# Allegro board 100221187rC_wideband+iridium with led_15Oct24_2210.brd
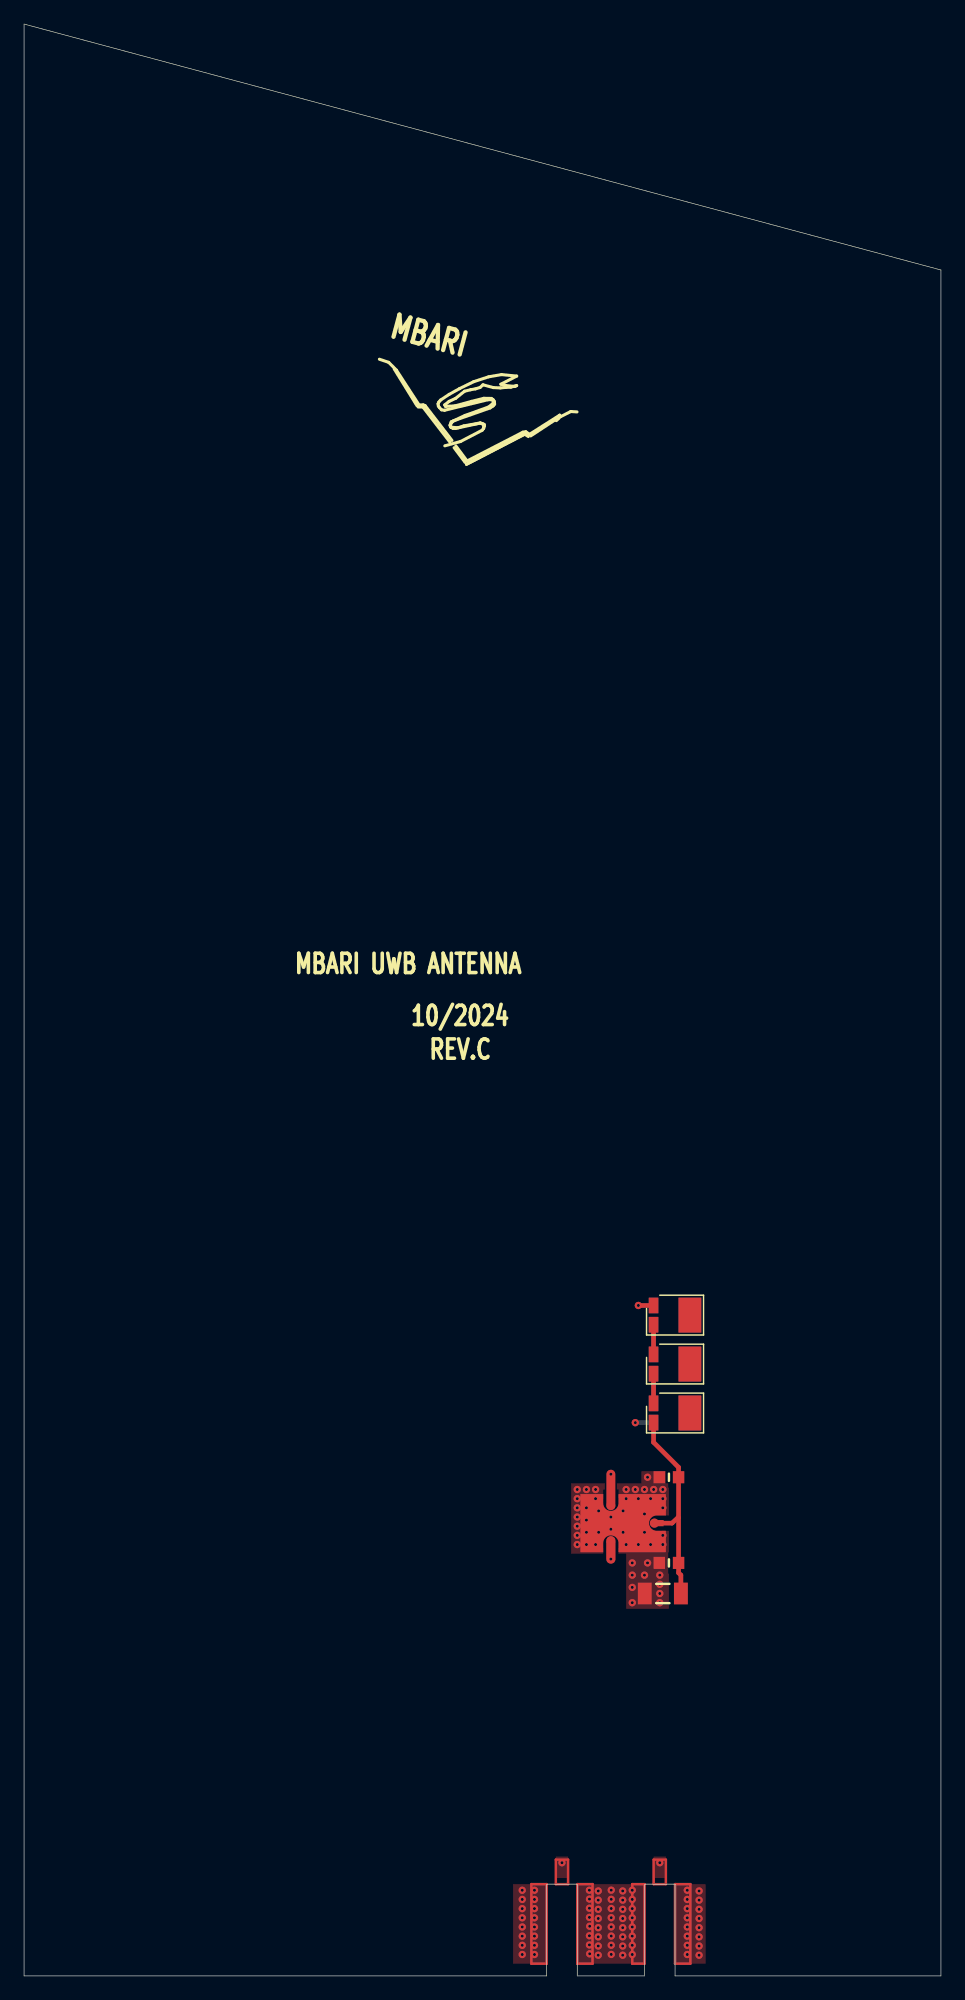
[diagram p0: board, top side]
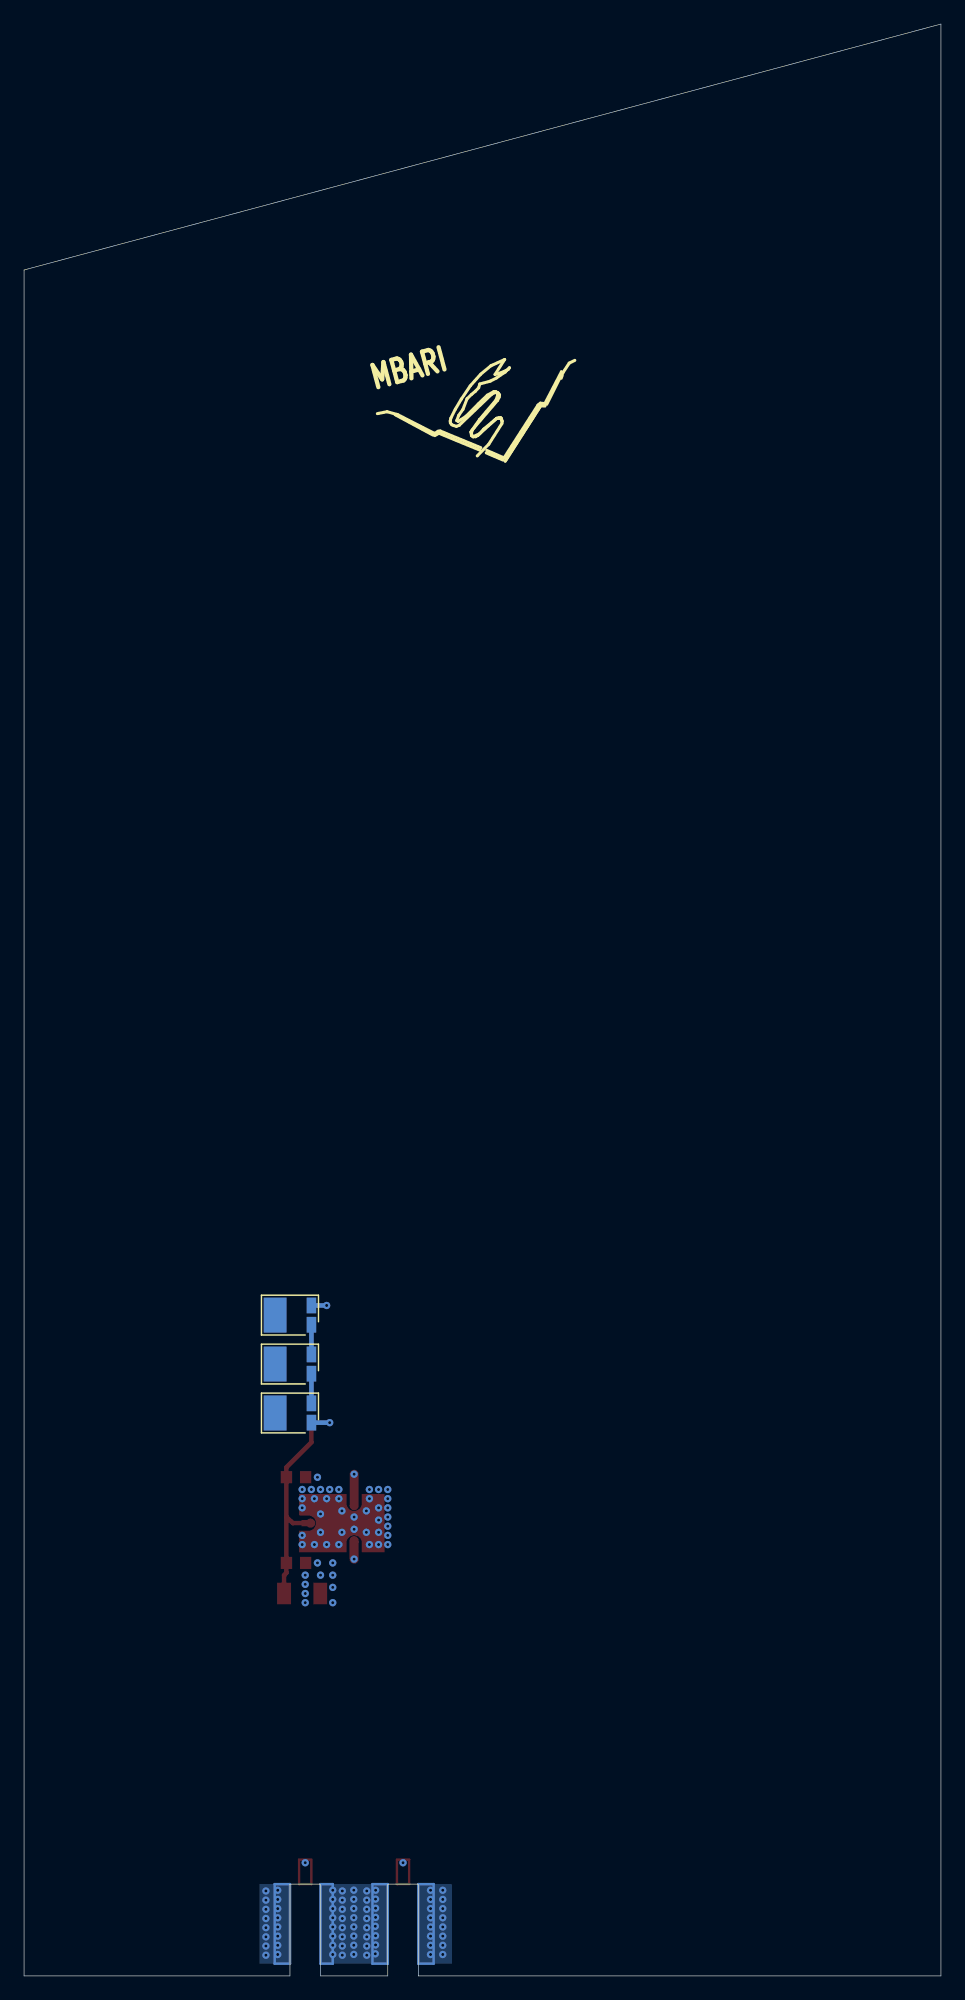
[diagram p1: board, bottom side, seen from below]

Outline 76.2 x 162.05 mm; copper layers: TOP, IN1, IN2, BOTTOM. Coordinates in mm from the lower left corner of the outline.
Outline path: 0,162.05 76.2,141.63 76.2,0 54.1,0 54.1,7.62 51.56,7.62 51.56,0 45.97,0 45.97,7.62 43.43,7.62 43.43,0 0,0 0,162.05

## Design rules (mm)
constraint set DEFAULT: min track width 0.127

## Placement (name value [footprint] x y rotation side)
C1  1.0uF  [CAPC3216X190N]  53.09 31.75 180 top
C2  10,000.0pF  [CAPC1608X87N]  53.59 41.4 180 top
C3  10,000.0pF  [CAPC1608X87N]  53.59 34.29 180 top
D1  LXM2-PH01-0070  [DIODFN449X305X210-3N]  54.1 46.74 0 top
D2  LXM2-PH01-0070  [DIODFN449X305X210-3N]  54.1 50.8 0 top
D3  LXM2-PH01-0070  [DIODFN449X305X210-3N]  54.1 54.86 0 top
D4  LXM2-PH01-0070  [DIODFN449X305X210-3N]  54.1 54.86 0 bottom
D5  LXM2-PH01-0070  [DIODFN449X305X210-3N]  54.1 50.8 0 bottom
D6  LXM2-PH01-0070  [DIODFN449X305X210-3N]  54.1 46.74 0 bottom
NOREF  -  []  12.7 145.54 0 top
NOREF#2  -  []  12.7 0 90 top
NOREF#3  -  []  52.83 0 0 top
NOREF#4  -  []  63.5 0 90 top
NOREF#5  -  []  51.69 0 0 top
NOREF#6  -  []  43.56 0 0 top
NOREF#7  -  []  -116.59 -69.6 0 top
NOREF#8  -  []  -116.59 -69.6 0 top
NOREF#9  -  []  45.85 0 0 top
NOREF#10  -  []  86.11 11.43 0 top
NOREF#11  -  []  39.12 134.37 345 top
NOREF#12  -  []  12.7 0 0 top
NOREF#13  -  []  38.61 134.62 165 bottom
U1  BT-0014SMG  [MARKI_BTSM-PDSM]  49.78 37.59 0 top

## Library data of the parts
C1-C3 = CAP
D1-D6 = LED_C1A2
U1 = MARKI_BT-0014SMG-1

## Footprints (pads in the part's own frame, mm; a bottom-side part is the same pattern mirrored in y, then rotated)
CAPC1608X87N
  rect 0.95x1.001 smd: 1(-0.8,0) 2(0.8,0)
CAPC3216X190N
  rect 1.151x1.801 smd: 1(-1.501,0) 2(1.501,0)
DIODFN449X305X210-3N
  rect 1.89x2.901 smd: (1.234,0)
  rect 0.79x1.3 smd: 1(-1.786,0.8) 2(-1.786,-0.8)
MARKI_BTSM-PDSM
  custom 0.191x0.191 smd: 1(-1.016,-1.651) 2(-1.016,1.651) 3(2.794,0)
  custom 1.206x1.206 smd: 4(0,0)

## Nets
GND_SIGNAL: C1.2 C2.2 C3.2 D6.1(C) U1.4(GND)
LED: C1.1 C2.1 C3.1 D1.2 U1.3
UWB FEEDLINE: U1.2
N06909: U1.1
N07165: D1.1(C) D2.2
N048171: D2.1(C) D3.2
N048451: D3.1(C) D4.2
N048711: D4.1(C) D5.2
N048971: D5.1(C) D6.2

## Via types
v1: diameter 0.61, hole 0.254, TOP to BOTTOM, 127 vias
v2: diameter 0.61, hole 0.254, IN1 to IN2, 1 via

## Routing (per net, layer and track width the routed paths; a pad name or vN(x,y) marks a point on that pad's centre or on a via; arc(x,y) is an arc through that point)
GND_SIGNAL: length 105.5
  IN1 w1.092: v1(52.83,9.4) 52.83,16.37 arc(53.51,19.78) 55.44,22.66 55.44,22.66 arc(58.77,27.65) 59.94,33.53 59.94,66.42 arc(58.56,70.98) 54.88,74.01 38.56,80.82 arc(35.76,83.47) 35.44,87.32 v2(38.1,96.77)
  BOTTOM w0.381: D6.1 v1(50.8,45.94)
  vias: v1(41.4,7.11) v1(41.4,6.35) v1(41.4,5.59) v1(41.4,4.83) v1(41.4,4.06) v1(41.4,3.3) v1(41.4,2.54) v1(41.4,1.78) v1(42.42,7.11) v1(42.42,6.35) v1(42.42,5.59) v1(42.42,4.83) v1(42.42,4.06) v1(42.42,3.3) v1(42.42,2.54) v1(42.42,1.78) v1(45.97,40.39) v1(45.97,39.62) v1(45.97,38.86) v1(45.97,38.1) v1(45.97,37.34) v1(45.97,36.58) v1(45.97,35.81) v1(46.74,40.39) v1(46.74,38.86) v1(46.74,37.85) v1(46.74,36.83) v1(46.74,35.81) v1(46.98,7.11) v1(46.99,6.38) v1(46.99,5.62) v1(46.99,4.86) v1(47.01,4.12) v1(46.99,3.34) v1(46.99,2.57) v1(47.01,1.84) v1(47.5,40.39) v1(47.5,39.62) v1(47.5,35.81) v1(47.72,7.05) v1(47.72,6.29) v1(47.72,5.53) v1(47.72,4.77) v1(47.72,4.01) v1(47.72,3.24) v1(47.72,2.48) v1(47.72,1.72) v1(47.75,38.61) v1(47.75,36.83) v1(48.77,38.1) v1(48.77,37.08) v1(48.8,7.12) v1(48.8,6.36) v1(48.8,5.6) v1(48.8,4.83) v1(48.8,4.07) v1(48.8,3.31) v1(48.8,2.55) v1(48.8,1.79) v1(49.78,38.61) v1(49.78,36.83) v1(49.75,7.05) v1(49.75,6.29) v1(49.75,5.53) v1(49.75,4.77) v1(49.75,4.01) v1(49.75,3.24) v1(49.75,2.48) v1(49.75,1.72) v1(50.04,40.39) v1(50.04,39.62) v1(50.04,35.81) v1(50.55,34.29) v1(50.55,33.27) v1(50.55,32.26) v1(50.55,30.99) v1(50.55,7.11) v1(50.55,6.35) v1(50.55,5.59) v1(50.55,4.83) v1(50.55,4.06) v1(50.55,3.3) v1(50.55,2.54) v1(50.55,1.78) v1(50.8,40.39) v1(51.05,39.62) v1(51.05,35.81) v1(51.56,40.39) v1(51.56,38.35) v1(51.56,36.83) v1(51.56,33.27) v1(51.82,41.4) v1(51.82,34.29) v1(52.07,39.62) v1(52.07,35.81) v1(52.32,40.39) v1(52.83,33.27) v1(52.83,32.51) v1(52.83,31.75) v1(52.83,30.99) v1(53.09,40.39) v1(53.09,39.62) v1(53.09,38.86) v1(53.09,36.58) v1(53.09,35.81) v1(55.12,7.11) v1(55.12,6.35) v1(55.12,5.59) v1(55.12,4.83) v1(55.12,4.06) v1(55.12,3.3) v1(55.12,2.54) v1(55.12,1.78) v1(56.1,7.05) v1(56.1,6.29) v1(56.1,5.53) v1(56.1,4.77) v1(56.1,4.01) v1(56.1,3.24) v1(56.1,2.48) v1(56.1,1.72)
LED: length 17.1
  TOP w0.381: 54.39,38.04 54.34,38.04 53.85,37.59 U1.3 ; 54.39,38.04 C2.1 54.39,42.22 52.32,44.3 D1.2 ; 54.39,38.04 C3.1 54.39,33.47 54.59,33.28 C1.1
UWB FEEDLINE: length 73.1
  TOP w0.737: U1.2 v1(48.77,41.66)
  IN1 w1.092: 28.7,103.12 24.76,88.23 arc(24.79,76.33) 30.74,66.03 44.28,52.5 arc(47.6,47.53) 48.77,41.66
N06909: length 28.2
  TOP w0.762: U1.1 v1(48.77,34.61)
  IN1 w1.092: v1(44.7,9.4) 44.7,25.07 arc(45.23,27.72) 46.74,29.97 arc(48.24,32.22) 48.77,34.88 v1(48.77,34.61)
N07165: length 2.5
  TOP w0.381: D2.2 D1.1
N048171: length 2.5
  TOP w0.381: D3.2 D2.1
N048451: length 2.5
  TOP w0.381: v1(51.05,55.66) D3.1
  BOTTOM w0.381: D3.1 v1(51.05,55.66)
N048711: length 2.5
  BOTTOM w0.381: D4.1 D5.2
N048971: length 2.5
  BOTTOM w0.381: D5.1 D6.2

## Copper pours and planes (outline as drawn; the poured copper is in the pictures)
GND_SIGNAL on TOP: 43.43,1.02 43.43,7.62 40.64,7.62 40.64,1.02
GND_SIGNAL on TOP: 50.04,30.48 50.04,35.05 45.47,35.05 45.47,40.89 51.31,40.89 51.31,41.91 53.34,41.91 53.34,40.89 53.59,40.89 53.59,30.48
GND_SIGNAL on TOP: 53.34,8.13 52.32,8.13 52.32,9.91 53.34,9.91
GND_SIGNAL on TOP: 45.97,7.62 45.97,1.02 51.56,1.02 51.56,7.62
GND_SIGNAL on TOP, BOTTOM: 54.1,7.62 54.1,1.02 56.64,1.02 56.64,7.62
GND_SIGNAL on BOTTOM: 40.64,7.62 40.64,1.02 43.43,1.02 43.43,7.62
GND_SIGNAL on BOTTOM: 45.97,1.02 45.97,7.62 51.56,7.62 51.56,1.02
GND_SIGNAL on IN2: 62.3,83.82 62.68,83.82 62.74,1.31 62.74,1.02 54.1,1.02 54.1,7.62 51.56,7.62 51.56,1.02 45.97,1.02 45.97,7.62 43.43,7.62 43.43,1.02 13.72,1.02 13.72,14.58 13.72,14.58 13.72,106.75 29.98,102.39 29.8,101.72 62.88,92.86 62.03,89.67 31.97,97.72 30.52,92.33 62.3,83.81 ; 2 cut-outs
UWB FEEDLINE on IN1: 62.2,131.03 13.77,144.01 28.64,102.66
N06909 on TOP: 45.21,8.13 44.2,8.13 44.2,9.91 45.21,9.91

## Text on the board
Ref Des/Silkscreen Top: MBARI UWB ANTENNA | 10/2024 | REV.C
XSECTION_CHART: *  PLATING: ENIG | L1: TOP CONDUCTOR - COPPER 2.1 MIL | *  DIELECTRIC - 4003C 32 mil | L2: IN1 CONDUCTOR - COPPER 1.4 MIL | *  DIELECTRIC - 4003C 20 mil | L3: IN2 CONDUCTOR - COPPER 1.4 MIL | L4: BOTTOM CONDUCTOR - COPPER 2.1 MIL | DESIGN CROSS SECTION CHART | ___________________________ | TOTAL THICKNESS 93 MIL | 1-4 | 2-3
PAGE_OUTLINE: CHANGE CABLE INPUT | ENLARGE OUTLINE, | c
DIMENSION: (2x) ADD EDGE PLATING INSIDE | BOTH SLOTS.
DEVICE_TYPE_BOTTOM: FIGURE | FINISHED_SIZE | 10.0 | DRILL CHART: TOP to BOTTOM | ALL UNITS ARE IN MILS | PLATED | QTY | 127
DEVICE_TYPE_TOP: FIGURE | FINISHED_SIZE | 10.0 | DRILL CHART: IN1 to IN2 | ALL UNITS ARE IN MILS | PLATED | QTY | 1
